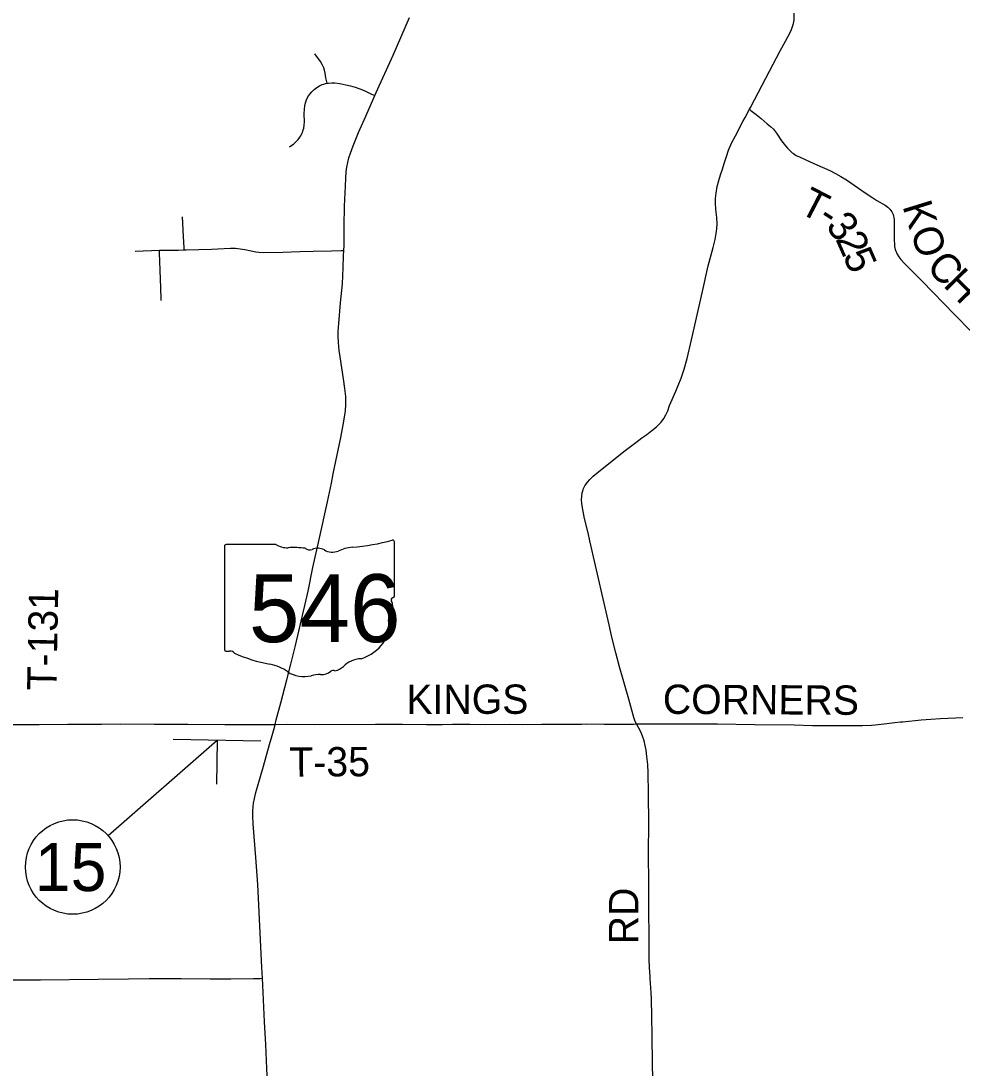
# Model space of a CAD drawing. Extents: x 40529 to 41139, y 15164 to 15584.
# Drawn here: x 40563.5 to 40618.2, y 15422.8 to 15483.8 of the extents above; entities that cross this region are included whole.
import ezdxf

# ---------------------------------------------------------------- set-up
doc = ezdxf.new("R2010")
doc.units = 0
for name, color, linetype in [('Default', 7, 'Continuous'), ('GM_X_County_Road', 7, 'Continuous'), ('GM_X_State_Location', 7, 'Continuous'), ('GM_X_State_Route', 7, 'Continuous'), ('GM_X_State_Shield', 7, 'Continuous'), ('GM_X_Township_Road', 7, 'Continuous'), ('GM_X_Township_Road_Text', 7, 'Continuous'), ('SH_Data', 7, 'Continuous'), ('SH_Text', 7, 'Continuous')]:
    doc.layers.add(name, color=color, linetype=linetype)

msp = doc.modelspace()

# ---------------------------------------------------------------- linework, layer by layer
at = {"layer": 'Default'}
for p, q in [((40577.414, 15441.873), (40572.318, 15441.955)), ((40574.866, 15441.914), (40574.825, 15439.366))]:
    msp.add_line(p, q, dxfattribs=at)
at = {"layer": 'GM_X_County_Road'}
msp.add_lwpolyline([(40562.496, 15442.839), (40562.743, 15442.842), (40563.673, 15442.836), (40564.51, 15442.842), (40566.187, 15442.85), (40568.14, 15442.858), (40569.258, 15442.865), (40571.214, 15442.863), (40573.169, 15442.857), (40575.312, 15442.834), (40577.638, 15442.839), (40578.104, 15442.84), (40578.247, 15442.84)], dxfattribs=at)
at = {"layer": 'GM_X_State_Route'}
for points in [[(40577.508, 15428.064), (40577.474, 15428.688), (40577.229, 15433.526), (40577.122, 15435.105), (40576.971, 15437.053), (40576.946, 15437.516), (40576.945, 15437.794), (40576.961, 15438.071), (40576.985, 15438.254), (40577.036, 15438.527), (40577.126, 15438.887), (40577.572, 15440.408), (40577.922, 15441.665), (40578.076, 15442.201), (40578.219, 15442.736), (40578.247, 15442.84), (40578.307, 15443.1), (40578.579, 15444.089), (40578.927, 15445.442), (40579.162, 15446.342), (40579.429, 15447.426), (40580.158, 15450.601), (40580.445, 15451.968), (40580.811, 15453.604), (40581.287, 15455.79), (40581.519, 15456.884), (40581.623, 15457.431), (40581.772, 15458.16), (40582.039, 15459.437), (40582.186, 15460.168), (40582.283, 15460.72), (40582.333, 15461.09), (40582.364, 15461.462), (40582.364, 15461.65), (40582.349, 15461.931), (40582.304, 15462.395), (40582.23, 15462.95), (40582.022, 15464.236), (40581.971, 15464.606), (40581.926, 15465.068), (40581.909, 15465.438), (40581.916, 15465.715), (40581.956, 15466.178), (40582.055, 15467.379), (40582.129, 15468.119), (40582.156, 15468.488), (40582.208, 15469.421), (40582.231, 15470.113), (40582.247, 15470.417), (40582.253, 15470.719), (40582.27, 15471.833), (40582.271, 15473.006), (40582.331, 15474.162), (40582.354, 15474.627), (40582.384, 15474.997), (40582.421, 15475.272), (40582.472, 15475.545), (40582.539, 15475.815), (40582.622, 15476.08), (40582.783, 15476.516), (40583.103, 15477.289), (40583.438, 15478.056), (40583.923, 15479.165), (40584.046, 15479.437), (40584.3, 15479.996), (40584.617, 15480.723), (40585.105, 15481.789), (40586.07, 15483.984)], [(40581.944, 15392.788), (40581.76, 15393.891), (40581.515, 15395.362), (40580.266, 15402.335), (40580.001, 15403.896), (40579.751, 15405.27), (40579.332, 15407.654), (40578.982, 15409.674), (40578.693, 15411.327), (40578.448, 15412.703), (40578.427, 15412.837), (40578.332, 15413.439), (40578.248, 15414.085), (40578.151, 15415.011), (40578.093, 15415.754), (40578.025, 15416.963), (40577.956, 15418.542), (40577.871, 15420.404), (40577.756, 15422.824), (40577.695, 15424.219), (40577.632, 15425.523), (40577.531, 15427.664), (40577.508, 15428.064)]]:
    msp.add_lwpolyline(points, dxfattribs=at)
at = {"layer": 'GM_X_State_Shield'}
for p, q in [((40575.295, 15453.208), (40575.295, 15447.205)), ((40578.288, 15453.312), (40575.392, 15453.312)), ((40585.183, 15450.32), (40585.183, 15453.46)), ((40585.182, 15450.321), (40585.183, 15450.32))]:
    msp.add_line(p, q, dxfattribs=at)
for centre, major_axis, start_param, end_param in [((40575.408, 15453.221), (0.115, 0), 1.712693, 3.28349), ((40578.978, 15454.009), (1.111, 0), 4.042523, 4.731795), ((40579.346, 15449.941), (3.989, 0), 1.404758, 1.657858), ((40580.722, 15452.558), (0.666, 0), 0.950623, 2.079405), ((40582.998, 15451.478), (2.11, 0), 1.699011, 2.107814), ((40581.661, 15461.497), (10.486, 0), 4.814394, 5.042369), ((40585.073, 15453.473), (0.11, 0), 6.141152, 7.989035), ((40580.252, 15453.252), (0.321, 0), 3.836095, 5.185415), ((40581.582, 15453.51), (0.802, 0), 4.081561, 5.145723), ((40585.157, 15450.089), (0.17, 0), 1.883978, 3.671073), ((40585.065, 15450.308), (0.118, 0), 5.05454, 6.418171), ((40584.074, 15449.692), (1.023, 0), 5.934695, 6.695948), ((40582.248, 15448.606), (2.623, 0), 5.101752, 6.440018), ((40585.577, 15449.006), (0.744, 0), 2.387724, 3.262537), ((40575.409, 15447.192), (0.116, 0), 3.00124, 4.508301), ((40575.427, 15447.806), (0.882, 0), 4.665946, 4.897461), ((40575.607, 15446.858), (0.318, 0), 0.519207, 1.627899), ((40579.622, 15452.252), (7.572, 0), 4.195997, 4.488961), ((40583.354, 15445.519), (1.436, 0), 1.647645, 2.488434), ((40577.365, 15444.508), (2.369, 0), 0.823519, 1.323587), ((40579.927, 15446.829), (1.503, 0), 4.026481, 4.996735), ((40580.906, 15446.379), (0.801, 0), 4.691044, 5.507374), ((40581.63, 15445.798), (0.226, 0), 1.147584, 2.315152), ((40581.534, 15446.623), (0.847, 0), 4.937069, 5.64225), ((40580.796, 15444.753), (1.235, 0), 1.495662, 1.94098)]:
    msp.add_ellipse(centre, major_axis=major_axis, ratio=0.8, start_param=start_param, end_param=end_param, dxfattribs=at)
at = {"layer": 'GM_X_Township_Road'}
msp.add_line((40570.1, 15470.389), (40571.517, 15470.432), dxfattribs=at)
for points in [[(40605.847, 15478.639), (40605.897, 15478.734), (40606.589, 15480.034), (40607.016, 15480.86), (40607.623, 15482.039), (40607.932, 15482.604), (40608.201, 15483.106), (40608.283, 15483.276), (40608.353, 15483.451), (40608.406, 15483.632), (40608.438, 15483.819), (40608.446, 15483.913), (40608.448, 15484.102), (40608.414, 15484.475), (40608.293, 15485.494), (40608.174, 15486.606), (40608.122, 15487.072), (40608.09, 15487.257), (40608.041, 15487.44), (40608.007, 15487.529), (40607.964, 15487.615), (40607.907, 15487.699)], [(40581.272, 15480.155), (40581.254, 15480.234), (40581.221, 15480.384), (40581.199, 15480.465), (40581.149, 15480.743), (40581.116, 15480.909), (40581.075, 15481.058), (40581.029, 15481.168), (40580.987, 15481.254), (40580.888, 15481.419), (40580.563, 15481.863)], [(40579.073, 15476.459), (40579.152, 15476.508), (40579.305, 15476.615), (40579.447, 15476.736), (40579.576, 15476.871), (40579.689, 15477.019), (40579.739, 15477.098), (40579.783, 15477.18), (40579.822, 15477.265), (40579.855, 15477.352), (40579.883, 15477.441), (40579.906, 15477.532), (40579.935, 15477.716), (40579.947, 15477.903), (40579.94, 15478.37), (40579.945, 15478.65), (40579.967, 15478.835), (40580.009, 15479.017), (40580.072, 15479.193), (40580.154, 15479.361), (40580.256, 15479.517), (40580.376, 15479.66), (40580.512, 15479.788), (40580.661, 15479.901), (40580.82, 15479.999), (40580.903, 15480.041), (40580.989, 15480.078), (40581.077, 15480.109), (40581.167, 15480.134), (40581.272, 15480.155)], [(40581.272, 15480.155), (40581.35, 15480.167), (40581.537, 15480.177), (40581.723, 15480.17), (40582, 15480.136), (40582.366, 15480.067), (40582.638, 15480.003), (40582.907, 15479.926), (40583.172, 15479.835), (40583.431, 15479.727), (40583.852, 15479.528), (40584.046, 15479.437)], [(40599.263, 15442.872), (40599.249, 15442.898), (40599.174, 15443.063), (40599.118, 15443.238), (40598.825, 15444.317), (40598.278, 15446.197), (40598.063, 15447.008), (40597.838, 15447.91), (40597.678, 15448.635), (40597.453, 15449.636), (40596.892, 15452.089), (40596.562, 15453.524), (40596.45, 15453.994), (40596.302, 15454.586), (40596.228, 15454.916), (40596.119, 15455.444), (40596.085, 15455.7), (40596.072, 15455.926), (40596.084, 15456.099), (40596.114, 15456.325), (40596.158, 15456.489), (40596.187, 15456.57), (40596.222, 15456.649), (40596.264, 15456.726), (40596.312, 15456.801), (40596.421, 15456.948), (40596.547, 15457.089), (40596.757, 15457.291), (40597.276, 15457.724), (40598.601, 15458.774), (40599.227, 15459.253), (40599.582, 15459.524), (40599.863, 15459.716), (40600.169, 15459.938), (40600.434, 15460.15), (40600.697, 15460.422), (40600.853, 15460.649), (40600.972, 15460.857), (40601.082, 15461.093), (40601.196, 15461.403), (40601.336, 15461.756), (40601.559, 15462.241), (40601.695, 15462.57), (40601.871, 15462.987), (40602.049, 15463.505), (40602.211, 15464.141), (40602.466, 15465.22), (40603.117, 15468.034), (40603.441, 15469.529), (40603.732, 15470.599), (40603.837, 15471.052), (40603.903, 15471.416), (40603.938, 15471.69), (40603.957, 15471.968), (40603.938, 15472.34), (40603.893, 15472.804), (40603.874, 15473.189), (40603.874, 15473.455), (40603.903, 15473.761), (40603.967, 15474.141), (40604.051, 15474.486), (40604.15, 15474.832), (40604.268, 15475.162), (40604.372, 15475.493), (40604.5, 15475.892), (40604.628, 15476.262), (40604.82, 15476.708), (40605.037, 15477.097), (40605.463, 15477.919), (40605.597, 15478.163), (40605.847, 15478.639)], [(40605.847, 15478.639), (40605.926, 15478.576), (40606.229, 15478.332), (40606.518, 15478.095), (40606.876, 15477.801), (40607.069, 15477.632), (40607.232, 15477.474), (40607.405, 15477.252), (40607.707, 15476.81), (40607.932, 15476.51), (40608.054, 15476.367), (40608.185, 15476.233), (40608.328, 15476.111), (40608.404, 15476.056), (40608.562, 15475.954), (40608.791, 15475.851), (40609.122, 15475.693), (40609.763, 15475.412), (40610.514, 15475.071), (40610.844, 15474.904), (40611.166, 15474.722), (40611.48, 15474.526), (40612.63, 15473.739), (40613.022, 15473.487), (40613.258, 15473.338), (40613.735, 15473.051), (40613.882, 15472.948), (40613.949, 15472.889), (40614.012, 15472.824), (40614.07, 15472.753), (40614.119, 15472.678), (40614.16, 15472.598), (40614.193, 15472.513), (40614.22, 15472.426), (40614.239, 15472.337), (40614.255, 15472.203), (40614.26, 15472.155)], [(40572.959, 15470.458), (40572.952, 15470.57), (40572.911, 15471.234), (40572.86, 15472.374)], [(40614.26, 15472.155), (40614.266, 15471.97), (40614.262, 15471.071), (40614.278, 15470.724)], [(40571.517, 15470.432), (40571.862, 15470.442), (40572.604, 15470.449), (40572.959, 15470.458)], [(40571.612, 15467.513), (40571.616, 15467.606), (40571.597, 15468.254), (40571.556, 15469.27), (40571.522, 15470.287), (40571.517, 15470.432)], [(40572.959, 15470.458), (40573.067, 15470.46), (40574.544, 15470.501), (40575.657, 15470.552), (40575.934, 15470.55), (40576.209, 15470.527), (40576.48, 15470.478), (40576.842, 15470.393), (40577.117, 15470.339), (40577.302, 15470.317), (40577.582, 15470.308), (40578.698, 15470.326), (40579.687, 15470.362), (40580.452, 15470.377), (40581.524, 15470.394), (40582.082, 15470.411), (40582.247, 15470.417)], [(40614.278, 15470.724), (40614.281, 15470.661), (40614.324, 15470.476), (40614.355, 15470.386), (40614.392, 15470.299), (40614.435, 15470.216), (40614.537, 15470.056), (40614.651, 15469.906), (40614.833, 15469.692), (40615.027, 15469.488), (40615.883, 15468.629), (40617.776, 15466.702), (40618.761, 15465.697)], [(40578.247, 15442.84), (40578.952, 15442.855), (40580.536, 15442.841), (40584.077, 15442.848), (40585.651, 15442.856), (40587.05, 15442.84), (40587.236, 15442.838), (40587.964, 15442.845), (40588.555, 15442.848), (40589.572, 15442.853), (40590.491, 15442.836), (40591.89, 15442.848), (40592.636, 15442.842), (40593.754, 15442.846), (40594.5, 15442.862), (40595.524, 15442.857), (40596.08, 15442.864), (40596.361, 15442.866), (40597.384, 15442.852), (40598.904, 15442.852), (40599.094, 15442.864), (40599.239, 15442.873), (40599.263, 15442.872)], [(40599.263, 15442.872), (40600.074, 15442.88), (40602.393, 15442.881), (40603.988, 15442.87), (40606.127, 15442.831), (40608.451, 15442.807), (40609.51, 15442.785), (40610.124, 15442.783), (40610.351, 15442.778), (40610.574, 15442.774), (40610.798, 15442.774), (40611.266, 15442.77), (40611.477, 15442.778), (40611.602, 15442.77), (40611.74, 15442.773), (40611.842, 15442.784), (40612.411, 15442.778), (40612.932, 15442.796), (40613.158, 15442.819), (40613.686, 15442.881), (40614.306, 15442.946), (40614.626, 15442.982), (40614.77, 15442.996)], [(40600.073, 15428.049), (40600.067, 15428.159), (40600.034, 15428.707), (40600.015, 15429.167), (40599.998, 15430.651), (40599.994, 15431.861), (40599.988, 15433.069), (40599.984, 15433.525), (40599.973, 15435.38), (40599.978, 15437.055), (40599.973, 15438.82), (40599.946, 15440.032), (40599.92, 15440.5), (40599.879, 15440.966), (40599.828, 15441.336), (40599.776, 15441.61), (40599.708, 15441.882), (40599.622, 15442.149), (40599.515, 15442.409), (40599.263, 15442.872)], [(40614.77, 15442.996), (40615.836, 15443.102), (40616.955, 15443.181), (40618.248, 15443.235)], [(40555.8, 15427.957), (40556.486, 15427.963), (40557.414, 15427.965), (40559.071, 15427.945), (40559.643, 15427.945), (40560.203, 15427.95), (40562.534, 15427.967), (40564.585, 15427.979), (40567.939, 15428.012), (40569.711, 15428.026), (40570.923, 15428.047), (40572.787, 15428.051), (40574.462, 15428.039), (40575.674, 15428.04), (40576.98, 15428.054), (40577.37, 15428.062), (40577.508, 15428.064)], [(40600.181, 15424.712), (40600.168, 15425.838), (40600.145, 15426.872), (40600.126, 15427.247), (40600.104, 15427.516), (40600.073, 15428.049)], [(40600.43, 15413), (40600.429, 15413.536), (40600.398, 15414.842), (40600.336, 15417.355), (40600.262, 15419.776), (40600.26, 15420.242), (40600.253, 15420.428), (40600.237, 15421.358), (40600.229, 15422.101), (40600.221, 15422.19), (40600.2, 15423.111), (40600.181, 15424.712)]]:
    msp.add_lwpolyline(points, dxfattribs=at)
at = {"layer": 'SH_Data'}
msp.add_line((40574.866, 15441.914), (40568.537, 15436.358), dxfattribs=at)
at = {"layer": 'SH_Text'}
msp.add_circle((40566.47, 15434.543), 2.75, dxfattribs=at)

# ---------------------------------------------------------------- texts
at = {"layer": 'GM_X_State_Location'}
for s in ['s', 'r']:
    msp.add_text(s, height=0.00568, dxfattribs=at).set_placement((40580.128, 15449.807))
msp.add_text('546', height=0.00568, rotation=0.00001, dxfattribs=at).set_placement((40578.122, 15449.394))
at = {"layer": 'GM_X_State_Shield'}
msp.add_text('546', height=3.9551, dxfattribs=at).set_placement((40576.718, 15447.628))
at = {"layer": 'GM_X_Township_Road_Text'}
for s, height, rotation, p in [('T', 1.706, 332.64146, (40608.647, 15472.659)), ('K', 1.706, 287.20692, (40614.729, 15473.009)), ('-', 1.706, 326.77325, (40609.741, 15472.096)), ('3', 1.706, 309.30919, (40610.225, 15471.803)), ('2', 1.706, 293.67348, (40610.827, 15471.095)), ('O', 1.706, 288.39596, (40615.185, 15471.537)), ('5', 1.706, 293.5546, (40611.248, 15470.133)), ('C', 1.706, 312.95688, (40616.064, 15469.431)), ('H', 1.706, 314.64574, (40617.057, 15468.366)), ('T-131', 1.7063, 88.87732, (40565.515, 15444.803)), ('KINGS', 1.7063, 0.00001, (40585.878, 15443.456)), ('CORNERS', 1.7063, 359.70307, (40600.798, 15443.456)), ('T-35', 1.7063, 0.35058, (40579.074, 15439.798)), ('RD', 1.7063, 90, (40599.371, 15430.046))]:
    msp.add_text(s, height=height, rotation=rotation, dxfattribs=at).set_placement(p)
at = {"layer": 'SH_Text'}
msp.add_text('15', height=2.8, dxfattribs=at).set_placement((40564.264, 15433.143))

doc.saveas('drawing.dxf')
